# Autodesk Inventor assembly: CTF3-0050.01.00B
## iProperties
Shininess: 64.0
Length Units: 11269
Angle Units: 11279
Time Units: 11290
Mass Units: 11283
Length Display Precision: 3
Angle Display Precision: 2
Compacted: True
Created: 2003-12
Part Number: CTF3-0050.01.00B
Document SubType Name: Assembly
Designer: Lollo
Density: 0.0
Volumn: 0.0
Area: 0.0
PropertySet Name: Model Information
Control State: 0
Master: False
Checked Out: False
Author: Lollo
